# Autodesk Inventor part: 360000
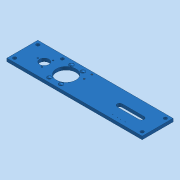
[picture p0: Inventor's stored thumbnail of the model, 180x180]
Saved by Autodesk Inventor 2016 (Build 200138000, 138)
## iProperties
Company: Mayer & Müller AG Schaltgeräte
Created: 2017-05
Part Number: 360000
Material: 1.0120
Document SubType Name: Modeling
Designer: I.Baliuc
Manufacturer: Standard
Standards Organization: Custom
Description: Seitenteil, Trenner
Density: 7.85 g/cm^3
Appearance: RAL 5012 Lichtblau
HalbzeugNorm: DIN 174
Zweck: Antriebseite: Motor-Standard
Abmessung: Fl. 120x12-525
Kopiert_von_Autor: CH
Kopie_erstellt_am: 2017-05-01T12:58:52
Kopiert_von_Datei: D:\Inventor-Tools Tutorial\Bauteile\3\36\364846.ipt
Kopie_Zieldatei: D:\Inventor-Tools Tutorial\Bauteile\3\36\360000.ipt
Author: CH
Keywords: 380125
Revision Number: 364846
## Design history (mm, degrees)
sketch "Skizze2"
  geometry: L1 (-170, 60)-(355, 60); L2 (355, 60)-(355, -60); L3 (355, -60)-(-170, -60); L4 (-170, -60)-(-170, 60); L5 (-222.5, 0)-(512.5, 0) reference; L6 (0, -72)-(0, 96) reference; L7 (292.5, 10)-(207.5, 10); L8 (207.5, -10)-(292.5, -10); C1 r 38 at (0, 0); A1 r 10 centre (292.5, 0) between (292.5, -10) and (292.5, 10); A2 r 10 centre (207.5, 0) between (207.5, 10) and (207.5, -10)
  constraints: 12 end point, 4 point on circle, 4 point on line, 3 centre point, 3 parallel, 2 tangent, 1 horizontal, 1 perpendicular, 2 other
  dimensions: "d4" = 170 distance between parallel lines of L4 L6; "d5" = 525 distance of L1.start L1.end; "d6" = 120 distance of L3.end L1.start; "d7" = 76 diameter of C1; "d8" = 85 distance of A2.centre A1.centre; "d9" = 20 distance between parallel lines of L7 L8; "d10" = 62.5 distance from line of L2 A1.centre
extrude "Extrusion2" new body sketch "Skizze2" distance "d11" = 12; taper "d12" = 0 deg
sketch "Skizze3"
  geometry: L1 (355, 60)-(355, -60) reference; L2 (-170, -60)-(-170, 60) reference; L3 (-222.5, 0)-(512.5, 0) reference; 4 further points
  constraints: 2 symmetric about line
  dimensions: "d13" = 90 distance of point (-155, -45) point (-155, 45); "d14" = 15 distance from line of point (-155, 45) L2; "d15" = 90 distance of point (340, -45) point (340, 45) (= d13); "d16" = 15 distance from line of point (340, 45) L1 (= d14)
hole "Bohrung_Ø13" sketch "Skizze3" at (-155, 45), (-155, -45), (340, -45), (340, 45) diameter "d17" = 13; stored, may be unused: countersink angle "d21" = 90 deg, drill point angle "d23" = 118 deg; dims "d18" = 6, "d19" = 4, "d20" = 2, "d22" = 8
sketch "Skizze4"
  geometry: L1 (-222.5, 0)-(512.5, 0) reference; L2 (0, -72)-(0, 96) reference; 4 further points
  constraints: 3 symmetric about line
  dimensions: "d24" = 85 distance of point (22.5, -42.5) point (22.5, 42.5); "d25" = 45 distance of point (-22.5, 42.5) point (22.5, 42.5)
hole "Bohrung2" sketch "Skizze4" at (22.5, 42.5), (22.5, -42.5), (-22.5, -42.5), (-22.5, 42.5) diameter "d26" = 16.5; stored, may be unused: countersink angle "d30" = 90 deg, drill point angle "d32" = 0 deg; dims "d27" = 6, "d28" = 16.5, "d29" = 0.4, "d31" = 0.7
sketch "Skizze5"
  geometry: C1 r 8.25 at (0, 0) reference; C2 r 8.25 at (0, -85) reference; C3 r 8.25 at (45, -85) reference; C4 r 8.25 at (45, 0) reference; 4 further points
  constraints: 4 coincident
hole "Bohrung3" sketch "Skizze5" at (0, 0), (45, 0), (45, -85), (0, -85) diameter "d33" = 8.4; stored, may be unused: countersink angle "d37" = 90 deg, drill point angle "d39" = 118 deg; dims "d34" = 6, "d35" = 16.5 (= d26), "d36" = 2, "d38" = 8
sketch "Skizze6" dims "d56" = 10
  geometry: L1 (-170, -60)-(-170, 60) reference; L2 (-222.5, 0)-(512.5, 0) reference; C1 r 38 at (0, 0) reference; 2 further points
  constraints: 1 vertical, 1 other
  dimensions: "d49" = 50 horizontal distance of point (50, 20) C1.centre; "d50" = 20 vertical distance of C1.centre point (50, 20); "d53" = 30 distance of point (50, 20) point (50, 50)
hole "Bohrung_M8" sketch "Skizze6" at (50, 20), (50, 50) diameter "d42" = 6.647; stored, may be unused: countersink angle "d46" = 90 deg, drill point angle "d48" = 118 deg; dims "d43" = 6, "d44" = 4, "d45" = 2, "d47" = 8
sketch "Skizze7"
  geometry: L1 (0, -72)-(0, 96) reference; L2 (-222.5, 0)-(512.5, 0) reference; 1 further point
  constraints: 1 point on line
  dimensions: "d58" = 85 distance from line of L1 point (-85, 0)
hole "Bohrung_Ø36" sketch "Skizze7" at (-85, 0) diameter "d59" = 36; stored, may be unused: countersink angle "d63" = 90 deg, drill point angle "d65" = 118 deg; dims "d60" = 6, "d61" = 4, "d62" = 2, "d64" = 8
sketch "Skizze8"
  geometry: L1 (-222.5, 0)-(512.5, 0) reference; C1 r 18 at (-85, 0) reference; 3 further points
  constraints: 1 point on line, 4 other
  dimensions: "d66" = 25 distance of point (-110, 0) C1.centre; "d69" = 360 deg dimension on C1.centre point (-110, 0) (derived)
hole "Bohrung_Ø5.5" sketch "Skizze8" at (-110, 0), (-72.5, -21.651), (-72.5, 21.651) diameter "d71" = 5.5; stored, may be unused: countersink angle "d75" = 90 deg, drill point angle "d77" = 118 deg; dims "d72" = 6, "d73" = 4, "d74" = 2, "d76" = 8
sketch "Skizze9"
  geometry: C1 r 18 at (-85, 0) reference; 1 further point
  dimensions: "d78" = 25 horizontal distance of point (-60, 45) C1.centre; "d79" = 45 vertical distance of C1.centre point (-60, 45)
hole "Bohrung_Ø12" sketch "Skizze9" at (-60, 45) diameter "d80" = 12; stored, may be unused: countersink angle "d84" = 90 deg, drill point angle "d86" = 118 deg; dims "d81" = 6, "d82" = 4, "d83" = 2, "d85" = 8
sketch "Skizze10" dims "d96" = 10
  geometry: L1 (355, 60)-(355, -60) reference; L2 (355, -60)-(-170, -60) reference; 4 further points
  constraints: 1 horizontal, 2 other
  dimensions: "d87" = 15 distance from line of L2 point (274, -45); "d88" = 81 distance from line of point (274, -45) L1; "d89" = 30 distance of point (274, -45) point (244, -45); "d90" = 15 distance from line of L2 point (244, -45) (= d87); "d93" = 18 distance of point (274, -45) point (256, -45)
hole "Bohrung_Ø2" sketch "Skizze10" at (274, -45), (244, -45), (256, -45), (226, -45) diameter "d98" = 2; stored, may be unused: countersink angle "d102" = 90 deg, drill point angle "d104" = 118 deg; dims "d99" = 6, "d100" = 4, "d101" = 2, "d103" = 8
node "Volumenkörper1"
node "Volumenkörpern"
node "Oberflächenkörpern"
node "Projizierte Kontur1"
